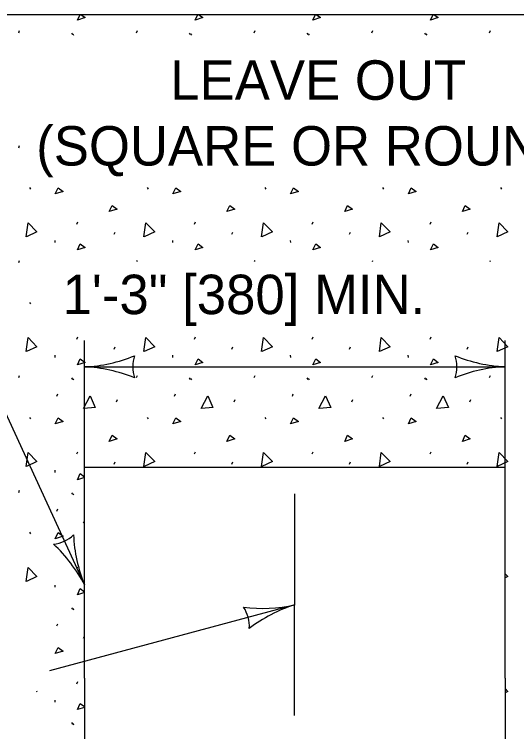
# Model space of a CAD drawing. Extents: x 49991.4 to 50021, y 49987.6 to 50011.4.
# Drawn here: x 50006.064 to 50006.829, y 49991.236 to 49992.327 of the extents above; entities that cross this region are included whole.
import ezdxf

# ---------------------------------------------------------------- set-up
doc = ezdxf.new("R2010")
doc.units = 0
for name, color, linetype in [('Level 1', 7, 'Continuous'), ('Level 2', 7, 'Continuous'), ('Level 3', 7, 'Continuous'), ('Level 5', 7, 'Continuous')]:
    doc.layers.add(name, color=color, linetype=linetype)

msp = doc.modelspace()

# ---------------------------------------------------------------- linework, layer by layer
at = {"layer": 'Level 1'}
for p, q in [((50005.3272, 49992.3269), (50007.655, 49992.3269)), ((50006.1602, 49992.3182), (50006.1644, 49992.3269)), ((50006.3394, 49992.3182), (50006.3436, 49992.3269)), ((50006.5185, 49992.3182), (50006.5227, 49992.3269)), ((50006.6977, 49992.3182), (50006.7019, 49992.3269)), ((50006.071, 49992.2988), (50006.0724, 49992.3022)), ((50006.2501, 49992.2988), (50006.2516, 49992.3022)), ((50006.4293, 49992.2988), (50006.4308, 49992.3022)), ((50006.6084, 49992.2988), (50006.6099, 49992.3022)), ((50006.7876, 49992.2988), (50006.7891, 49992.3022)), ((50006.1511, 49992.2983), (50006.1526, 49992.2961)), ((50006.1531, 49992.2975), (50006.1546, 49992.2953)), ((50006.3303, 49992.2983), (50006.3318, 49992.2961)), ((50006.3323, 49992.2975), (50006.3338, 49992.2953)), ((50006.5095, 49992.2983), (50006.511, 49992.2961)), ((50006.5115, 49992.2975), (50006.513, 49992.2953)), ((50006.6886, 49992.2983), (50006.6901, 49992.2961)), ((50006.6906, 49992.2975), (50006.6921, 49992.2953)), ((50006.071, 49992.1241), (50006.0724, 49992.1275)), ((50006.0874, 49992.0635), (50006.0889, 49992.0613)), ((50006.1265, 49992.0538), (50006.131, 49992.0632)), ((50006.131, 49992.0632), (50006.1385, 49992.0576)), ((50006.2665, 49992.0635), (50006.268, 49992.0613)), ((50006.3057, 49992.0538), (50006.3102, 49992.0632)), ((50006.3102, 49992.0632), (50006.3176, 49992.0576)), ((50006.4457, 49992.0635), (50006.4472, 49992.0613)), ((50006.4848, 49992.0538), (50006.4893, 49992.0632)), ((50006.4893, 49992.0632), (50006.4968, 49992.0576)), ((50006.6248, 49992.0635), (50006.6263, 49992.0613)), ((50006.664, 49992.0538), (50006.6685, 49992.0632)), ((50006.6685, 49992.0632), (50006.6759, 49992.0576)), ((50006.804, 49992.0635), (50006.8055, 49992.0613)), ((50006.1385, 49992.0576), (50006.1265, 49992.0538)), ((50006.3176, 49992.0576), (50006.3057, 49992.0538)), ((50006.4968, 49992.0576), (50006.4848, 49992.0538)), ((50006.6759, 49992.0576), (50006.664, 49992.0538)), ((50006.1595, 49992.008), (50006.161, 49992.0113)), ((50006.3386, 49992.008), (50006.3401, 49992.0113)), ((50006.5178, 49992.008), (50006.5193, 49992.0113)), ((50006.697, 49992.008), (50006.6985, 49992.0113)), ((50006.2162, 49991.9927), (50006.2177, 49991.996)), ((50006.3953, 49991.9927), (50006.3968, 49991.996)), ((50006.5745, 49991.9927), (50006.576, 49991.996)), ((50006.7537, 49991.9927), (50006.7551, 49991.996)), ((50006.1257, 49991.9833), (50006.1261, 49991.9799)), ((50006.3048, 49991.9833), (50006.3052, 49991.9799)), ((50006.484, 49991.9833), (50006.4844, 49991.9799)), ((50006.6632, 49991.9833), (50006.6635, 49991.9799)), ((50006.071, 49991.9494), (50006.0724, 49991.9528)), ((50006.2509, 49991.9511), (50006.2516, 49991.9528)), ((50006.43, 49991.9511), (50006.4308, 49991.9528)), ((50006.6092, 49991.9511), (50006.6099, 49991.9528)), ((50006.7883, 49991.9511), (50006.7891, 49991.9528)), ((50006.0874, 49991.8888), (50006.0889, 49991.8866)), ((50006.1595, 49991.8332), (50006.161, 49991.8366)), ((50006.3386, 49991.8332), (50006.3401, 49991.8366)), ((50006.5178, 49991.8332), (50006.5193, 49991.8366)), ((50006.697, 49991.8332), (50006.6985, 49991.8366)), ((50006.2162, 49991.8179), (50006.2177, 49991.8213)), ((50006.3953, 49991.8179), (50006.3968, 49991.8213)), ((50006.5745, 49991.8179), (50006.576, 49991.8213)), ((50006.7537, 49991.8179), (50006.7551, 49991.8213)), ((50006.1257, 49991.8086), (50006.1261, 49991.8052)), ((50006.3048, 49991.8086), (50006.3052, 49991.8052)), ((50006.484, 49991.8086), (50006.4844, 49991.8052)), ((50006.6632, 49991.8086), (50006.6635, 49991.8052)), ((50006.071, 49991.7747), (50006.0724, 49991.778)), ((50006.2501, 49991.7747), (50006.2516, 49991.778)), ((50006.4293, 49991.7747), (50006.4308, 49991.778)), ((50006.6084, 49991.7747), (50006.6099, 49991.778)), ((50006.7876, 49991.7747), (50006.7891, 49991.778)), ((50006.1511, 49991.7742), (50006.1526, 49991.7719)), ((50006.1531, 49991.7733), (50006.1546, 49991.7711)), ((50006.3303, 49991.7742), (50006.3318, 49991.7719)), ((50006.3323, 49991.7733), (50006.3338, 49991.7711)), ((50006.5095, 49991.7742), (50006.511, 49991.7719)), ((50006.5115, 49991.7733), (50006.513, 49991.7711)), ((50006.6886, 49991.7742), (50006.6901, 49991.7719)), ((50006.6906, 49991.7733), (50006.6921, 49991.7711)), ((50006.1291, 49991.7465), (50006.1306, 49991.7499)), ((50006.3083, 49991.7465), (50006.3098, 49991.7499)), ((50006.4875, 49991.7465), (50006.4889, 49991.7499)), ((50006.6666, 49991.7465), (50006.6681, 49991.7499)), ((50006.2199, 49991.738), (50006.2214, 49991.7413)), ((50006.3991, 49991.738), (50006.4006, 49991.7413)), ((50006.5782, 49991.738), (50006.5797, 49991.7413)), ((50006.7574, 49991.738), (50006.7589, 49991.7413)), ((50006.0874, 49991.7141), (50006.0889, 49991.7118)), ((50006.1265, 49991.7044), (50006.131, 49991.7137)), ((50006.131, 49991.7137), (50006.1385, 49991.7081)), ((50006.2665, 49991.7141), (50006.268, 49991.7118)), ((50006.3057, 49991.7044), (50006.3102, 49991.7137)), ((50006.3102, 49991.7137), (50006.3176, 49991.7081)), ((50006.4457, 49991.7141), (50006.4472, 49991.7118)), ((50006.4848, 49991.7044), (50006.4893, 49991.7137)), ((50006.4893, 49991.7137), (50006.4968, 49991.7081)), ((50006.6248, 49991.7141), (50006.6263, 49991.7118)), ((50006.664, 49991.7044), (50006.6685, 49991.7137)), ((50006.6685, 49991.7137), (50006.6759, 49991.7081)), ((50006.804, 49991.7141), (50006.8055, 49991.7118)), ((50006.1385, 49991.7081), (50006.1265, 49991.7044)), ((50006.3176, 49991.7081), (50006.3057, 49991.7044)), ((50006.4968, 49991.7081), (50006.4848, 49991.7044)), ((50006.6759, 49991.7081), (50006.664, 49991.7044)), ((50006.1595, 49991.6585), (50006.161, 49991.6619)), ((50006.3386, 49991.6585), (50006.3401, 49991.6619)), ((50006.5178, 49991.6585), (50006.5193, 49991.6619)), ((50006.697, 49991.6585), (50006.6985, 49991.6619)), ((50006.2162, 49991.6432), (50006.2177, 49991.6466)), ((50006.3953, 49991.6432), (50006.3968, 49991.6466)), ((50006.5745, 49991.6432), (50006.576, 49991.6466)), ((50006.7537, 49991.6432), (50006.7551, 49991.6466)), ((50006.1711, 49991.3177), (50006.1711, 49991.6377)), ((50006.8111, 49991.6377), (50006.1711, 49991.6377)), ((50006.8111, 49991.3177), (50006.8111, 49991.6377)), ((50006.1257, 49991.6339), (50006.1261, 49991.6305)), ((50006.1711, 49991.6228), (50006.1602, 49991.6194)), ((50006.071, 49991.6), (50006.0724, 49991.6033)), ((50006.1511, 49991.5995), (50006.1526, 49991.5972)), ((50006.1531, 49991.5986), (50006.1546, 49991.5964)), ((50006.1291, 49991.5718), (50006.1306, 49991.5752)), ((50006.1696, 49991.5532), (50006.1711, 49991.5561)), ((50006.1711, 49991.5533), (50006.1699, 49991.5532)), ((50006.0874, 49991.5394), (50006.0889, 49991.5371)), ((50006.1265, 49991.5297), (50006.131, 49991.539)), ((50006.131, 49991.539), (50006.1385, 49991.5334)), ((50006.1385, 49991.5334), (50006.1265, 49991.5297)), ((50006.1595, 49991.4838), (50006.161, 49991.4871)), ((50006.1257, 49991.4591), (50006.1261, 49991.4558)), ((50006.1711, 49991.448), (50006.1602, 49991.4446)), ((50006.1511, 49991.4247), (50006.1526, 49991.4225)), ((50006.1531, 49991.4239), (50006.1546, 49991.4216)), ((50006.1291, 49991.3971), (50006.1306, 49991.4004)), ((50006.1696, 49991.3784), (50006.1711, 49991.3814)), ((50006.1711, 49991.3785), (50006.1699, 49991.3784)), ((50006.1265, 49991.3549), (50006.131, 49991.3643)), ((50006.131, 49991.3643), (50006.1385, 49991.3587)), ((50006.1385, 49991.3587), (50006.1265, 49991.3549)), ((50006.1595, 49991.3091), (50006.161, 49991.3124)), ((50006.1711, 49991.3177), (50006.1711, 49990.9977)), ((50006.8111, 49991.3177), (50006.8111, 49990.9977)), ((50006.1257, 49991.2844), (50006.1261, 49991.2811)), ((50006.1711, 49991.2733), (50006.1602, 49991.2699)), ((50006.1511, 49991.25), (50006.1526, 49991.2478)), ((50006.1531, 49991.2492), (50006.1546, 49991.2469))]:
    msp.add_line(p, q, dxfattribs=at)
for points in [[(50006.1656, 49992.3269), (50006.1722, 49992.322), (50006.1602, 49992.3182)], [(50006.3447, 49992.3269), (50006.3513, 49992.322), (50006.3394, 49992.3182)], [(50006.5239, 49992.3269), (50006.5305, 49992.322), (50006.5185, 49992.3182)], [(50006.703, 49992.3269), (50006.7096, 49992.322), (50006.6977, 49992.3182)], [(50006.2088, 49992.0272), (50006.2133, 49992.0365), (50006.2207, 49992.0309), (50006.2088, 49992.0272)], [(50006.3879, 49992.0272), (50006.3924, 49992.0365), (50006.3999, 49992.0309), (50006.3879, 49992.0272)], [(50006.5671, 49992.0272), (50006.5716, 49992.0365), (50006.579, 49992.0309), (50006.5671, 49992.0272)], [(50006.7463, 49992.0272), (50006.7507, 49992.0365), (50006.7582, 49992.0309), (50006.7463, 49992.0272)], [(50006.0824, 49991.9888), (50006.0853, 49992.0101), (50006.0987, 49991.9963), (50006.0827, 49991.9889)], [(50006.2616, 49991.9888), (50006.2645, 49992.0101), (50006.2779, 49991.9963), (50006.2619, 49991.9889)], [(50006.4407, 49991.9888), (50006.4437, 49992.0101), (50006.457, 49991.9963), (50006.4411, 49991.9889)], [(50006.6199, 49991.9888), (50006.6228, 49992.0101), (50006.6362, 49991.9963), (50006.6202, 49991.9889)], [(50006.799, 49991.9888), (50006.802, 49992.0101), (50006.8153, 49991.9963), (50006.7994, 49991.9889)], [(50006.1602, 49991.9688), (50006.1647, 49991.9781), (50006.1722, 49991.9725), (50006.1602, 49991.9688)], [(50006.3394, 49991.9688), (50006.3439, 49991.9781), (50006.3513, 49991.9725), (50006.3394, 49991.9688)], [(50006.5185, 49991.9688), (50006.523, 49991.9781), (50006.5305, 49991.9725), (50006.5185, 49991.9688)], [(50006.6977, 49991.9688), (50006.7022, 49991.9781), (50006.7096, 49991.9725), (50006.6977, 49991.9688)], [(50006.0824, 49991.8141), (50006.0853, 49991.8354), (50006.0987, 49991.8216), (50006.0827, 49991.8142)], [(50006.2616, 49991.8141), (50006.2645, 49991.8354), (50006.2779, 49991.8216), (50006.2619, 49991.8142)], [(50006.4407, 49991.8141), (50006.4437, 49991.8354), (50006.457, 49991.8216), (50006.4411, 49991.8142)], [(50006.6199, 49991.8141), (50006.6228, 49991.8354), (50006.6362, 49991.8216), (50006.6202, 49991.8142)], [(50006.799, 49991.8141), (50006.802, 49991.8354), (50006.8153, 49991.8216), (50006.7994, 49991.8142)], [(50006.1602, 49991.7941), (50006.1647, 49991.8034), (50006.1722, 49991.7978), (50006.1602, 49991.7941)], [(50006.3394, 49991.7941), (50006.3439, 49991.8034), (50006.3513, 49991.7978), (50006.3394, 49991.7941)], [(50006.5185, 49991.7941), (50006.523, 49991.8034), (50006.5305, 49991.7978), (50006.5185, 49991.7941)], [(50006.6977, 49991.7941), (50006.7022, 49991.8034), (50006.7096, 49991.7978), (50006.6977, 49991.7941)], [(50006.1696, 49991.7279), (50006.1796, 49991.7469), (50006.1875, 49991.7294), (50006.1699, 49991.7279)], [(50006.3487, 49991.7279), (50006.3588, 49991.7469), (50006.3666, 49991.7294), (50006.3491, 49991.7279)], [(50006.5279, 49991.7279), (50006.5379, 49991.7469), (50006.5458, 49991.7294), (50006.5282, 49991.7279)], [(50006.707, 49991.7279), (50006.7171, 49991.7469), (50006.7249, 49991.7294), (50006.7074, 49991.7279)], [(50006.2088, 49991.6777), (50006.2133, 49991.6871), (50006.2207, 49991.6815), (50006.2088, 49991.6777)], [(50006.3879, 49991.6777), (50006.3924, 49991.6871), (50006.3999, 49991.6815), (50006.3879, 49991.6777)], [(50006.5671, 49991.6777), (50006.5716, 49991.6871), (50006.579, 49991.6815), (50006.5671, 49991.6777)], [(50006.7463, 49991.6777), (50006.7507, 49991.6871), (50006.7582, 49991.6815), (50006.7463, 49991.6777)], [(50006.0824, 49991.6394), (50006.0853, 49991.6607), (50006.0987, 49991.6469), (50006.0827, 49991.6395)], [(50006.2616, 49991.6394), (50006.2645, 49991.6607), (50006.2779, 49991.6469), (50006.2619, 49991.6395)], [(50006.4407, 49991.6394), (50006.4437, 49991.6607), (50006.457, 49991.6469), (50006.4411, 49991.6395)], [(50006.6199, 49991.6394), (50006.6228, 49991.6607), (50006.6362, 49991.6469), (50006.6202, 49991.6395)], [(50006.799, 49991.6394), (50006.802, 49991.6607), (50006.8153, 49991.6469), (50006.7994, 49991.6395)], [(50006.1602, 49991.6194), (50006.1647, 49991.6287), (50006.1711, 49991.6239)], [(50006.0824, 49991.4646), (50006.0853, 49991.486), (50006.0987, 49991.4722), (50006.0827, 49991.4648)], [(50006.8111, 49991.4765), (50006.8153, 49991.4722), (50006.8111, 49991.4702)], [(50006.1602, 49991.4446), (50006.1647, 49991.454), (50006.1711, 49991.4491)], [(50006.0978, 49991.2984), (50006.0987, 49991.2974), (50006.0978, 49991.297)], [(50006.8111, 49991.3018), (50006.8153, 49991.2974), (50006.8111, 49991.2955)], [(50006.1602, 49991.2699), (50006.1647, 49991.2792), (50006.1711, 49991.2744)]]:
    msp.add_lwpolyline(points, dxfattribs=at)
at = {"layer": 'Level 3'}
for p, q in [((50005.8488, 49992.157), (50006.1711, 49991.4594)), ((50006.1711, 49991.5977), (50006.1711, 49991.8311)), ((50006.8111, 49991.5977), (50006.8111, 49991.8311)), ((50006.1711, 49991.7911), (50006.8111, 49991.7911)), ((50006.491, 49991.4293), (50006.1178, 49991.3286))]:
    msp.add_line(p, q, dxfattribs=at)
for centre, radius, start, end in [((50006.162, 49992.0132), 0.2223, 272.3605, 292.544), ((50006.2993, 49991.7911), 0.0548, 162.1388, 197.8612), ((50006.6829, 49991.7911), 0.0548, 342.1388, 17.8612), ((50006.8226, 49992.0238), 0.233, 247.9228, 267.1727), ((50006.1596, 49991.5584), 0.233, 67.9228, 87.1727), ((50006.8203, 49991.569), 0.2223, 92.3605, 112.544), ((50006.1173, 49991.5758), 0.0548, 276.9383, 312.6607), ((50006.3766, 49991.5443), 0.2223, 182.2555, 202.439), ((50005.9647, 49991.3514), 0.233, 27.6268, 46.8766), ((50006.442, 49991.6461), 0.2223, 262.5575, 282.741), ((50006.5627, 49991.2076), 0.233, 107.9288, 127.1786), ((50006.3672, 49991.3959), 0.0548, 357.2403, 32.9627)]:
    msp.add_arc(centre, radius, start, end, dxfattribs=at)
at = {"layer": 'Level 5'}
msp.add_line((50006.4909, 49991.2609), (50006.4911, 49991.5977), dxfattribs=at)

# ---------------------------------------------------------------- texts
at = {"layer": 'Level 2'}
for s, p in [('LEAVE OUT', (50006.3016, 49992.197)), ('(SQUARE OR ROUND)', (50006.0976, 49992.097)), ('1\'-3" [380] MIN.', (50006.1376, 49991.8711))]:
    msp.add_text(s, height=0.06, dxfattribs=at).set_placement(p)

doc.saveas('drawing.dxf')
